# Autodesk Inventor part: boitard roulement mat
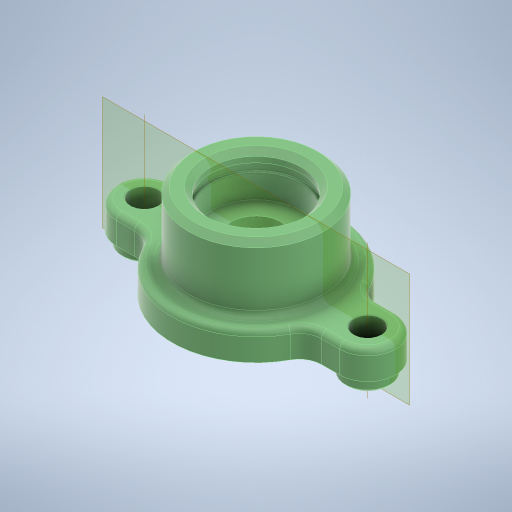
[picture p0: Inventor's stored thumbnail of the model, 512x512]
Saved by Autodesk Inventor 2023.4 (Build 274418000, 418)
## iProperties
Created: 2023-11
Part Number: boitard roulement mat
Material: Plastique ABS
Document SubType Name: Modeling
Designer: mel
Density: 1.06 g/cm^3
Appearance: Lisse - Vert forêt foncé
Author: mel
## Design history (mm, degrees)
sketch "Esquisse1"
  geometry: L1 (0, 0)-(12, 0); L2 (12, 0)-(12, 13); L3 (8.6, 13.2)-(8.1, 13.2); L4 (0, 9)-(0, 0); L5 (0, 0)-(8.1, 0); L6 (8.1, 0)-(8.1, 4.2); L7 (8.1, 4.2)-(4.5, 4.2); L8 (0, 4)-(0, 0); L9 (8.1, 13.2)-(8.1, 9); L10 (8.1, 9)-(4.5, 9); L11 (0, 9)-(0, 13); L12 (4.5, 9)-(4.5, 4.2); L13 (8.1, 13.2)-(8.6, 13.2); L14 (8.6, 13.2)-(8.6, 14.7); L15 (8.6, 14.7)-(8.1, 14.7); L16 (0, 12.692)-(0, 13); L17 (8.1, 14.7)-(8.6, 14.7); L18 (12, 14.7)-(12, 16.7); L19 (12, 16.7)-(8.1, 16.7); L20 (8.1, 16.7)-(8.1, 14.7); L21 (12, 14.7)-(12, 13); 1 further point
  constraints: 42 end point, 9 parallel, 5 perpendicular, 4 horizontal, 1 point on line, 1 vertical
  dimensions: "d1" = 4.2 distance of L6.end L5.end; "d2" = 12 distance between parallel lines of L2 L4; "d4" = 4.2 distance between parallel lines of L3 L10 (= d1); "d5" = 4.8 distance between parallel lines of L7 L10 (derived); "d6" = 4.5 distance between parallel lines of L12 L4; "d8" = 1.5 distance of L14.end L3.start; "d9" = 2 distance of L18.end L18.start; "d35" = 8.1 distance between parallel lines of L8 L6; "d36" = 8.1 distance between parallel lines of L4 L9 (= d35); "d37" = 8.6 distance between parallel lines of L14 L8
revolve "Révolution1" sketch "Esquisse1" stored, may be unused: angle "d10" = 90 deg
chamfer "Chanfrein1" distance "d11" = 1; stored, may be unused: second distance "d12" = 2, angle "d13" = 45 deg
sketch "Esquisse2"
  geometry: L1 (-20, 5)-(-16.733, 5); L2 (16.733, 5)-(20, 5); L3 (20, -5)-(16.733, -5); L4 (-16.733, -5)-(-20, -5); C1 r 2.5 at (-20, 0); C2 r 2.5 at (20, 0); C3 r 8.1 at (0, 0) reference; A1 r 5 centre (-20, 0) between (-20, 5) and (-20, -5); A2 r 5 centre (20, 0) between (20, -5) and (20, 5); A3 r 15 centre (0, 0) between (-13.21, -7.105) and (13.21, -7.105); A4 r 15 centre (0, 0) between (13.21, 7.105) and (-13.21, 7.105); A5 r 4 centre (-16.733, 9) between (-16.733, 5) and (-13.21, 7.105); A6 r 4 centre (-16.733, -9) between (-13.21, -7.105) and (-16.733, -5); A7 r 4 centre (16.733, -9) between (16.733, -5) and (13.21, -7.105); A8 r 4 centre (16.733, 9) between (13.21, 7.105) and (16.733, 5); 5 further points
  constraints: 20 point on circle, 10 centre point, 8 end point, 8 tangent, 4 parallel, 4 point on line, 3 coincident, 2 equal radius, 2 horizontal
  dimensions: "d15" = 10 diameter of A1; "d16" = 10 diameter of A2 (= d15); "d17" = 4 radius of A5; "d18" = 4 radius of A7 (derived); "d19" = 5 diameter of C1; "d20" = 5 diameter of C2
extrude "Extrusion1" join sketch "Esquisse2" distance "d21" = 5; taper "d22" = 0 deg
fillet "Congé1" dims "d23" = 1
fillet "Congé2" dims "d24" = 1
chamfer "Chanfrein2" distance "d25" = 1; stored, may be unused: second distance "d26" = 2, angle "d27" = 45 deg
sketch "Esquisse3"
  geometry: C1 r 2.5 at (20, 0) reference; C2 r 2.5 at (-20, 0) reference; C3 r 4 at (20, 0); C4 r 4 at (-20, 0); 1 further point
  constraints: 2 centre point, 2 coincident
  dimensions: "d28" = 8 diameter of C3; "d29" = 8 diameter of C4
extrude "Extrusion2" join sketch "Esquisse3" distance "d30" = 2.5; taper "d31" = 0 deg
chamfer "Chanfrein3" distance "d32" = 0.5; stored, may be unused: second distance "d33" = 2, angle "d34" = 45 deg
node "Plan de construction2"
  node "Axe de construction3"
  node "Axe de construction4"
feature "Ş耀Š耀Ţ耀Ť耀Ŧ耀Ũ耀Ū耀Ŭ耀" dims "d1" = 4.2, "d2" = 12, "d4" = 4.2 (= d1), "d5" = 4.8 (derived), "d6" = 4.5, "d8" = 1.5, "d9" = 2, "d10" = 90 deg, "d11" = 1, "d12" = 2, "d13" = 45 deg, "d14" = 30, "d15" = 10, "d16" = 10 (= d15), "d17" = 4, "d18" = 4 (derived), "d19" = 5, "d20" = 5, "d21" = 5, "d22" = 0, "d23" = 1, "d24" = 1, "d25" = 1, "d26" = 2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
node "Solide1"
